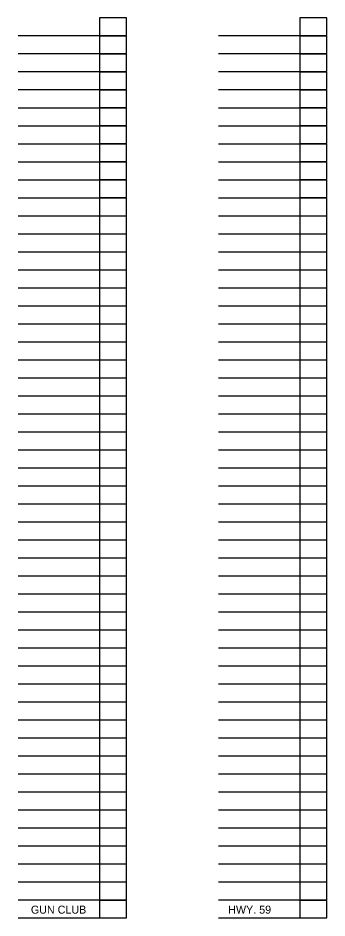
# Model space of a CAD drawing. Extents: x 625451 to 4181825, y 337941 to 441164.
# Drawn here: x 719151 to 726863, y 373673 to 396164 of the extents above; entities that cross this region are included whole.
import ezdxf

# ---------------------------------------------------------------- set-up
doc = ezdxf.new("R2010")
doc.units = 0
for name, color, linetype in [('PLOT_BDR-NOTUSED', 7, 'Continuous'), ('R_CX_LAYOUT-GC', 7, 'Continuous'), ('R_CX_Layout-Hwy59', 7, 'Continuous'), ('R_No Plot_SEG2_FR', 7, 'Continuous')]:
    doc.layers.add(name, color=color, linetype=linetype)

msp = doc.modelspace()

# ---------------------------------------------------------------- linework, layer by layer
at = {"layer": 'PLOT_BDR-NOTUSED'}
for points in [[(721862, 396164), (721182, 396164), (721182, 395724), (721862, 395724)], [(726863, 396164), (726183, 396164), (726183, 395724), (726863, 395724)], [(721862, 395714), (721182, 395714), (721182, 395274), (721862, 395274)], [(726863, 395714), (726183, 395714), (726183, 395274), (726863, 395274)], [(721862, 395264), (721182, 395264), (721182, 394824), (721862, 394824)], [(726863, 395264), (726183, 395264), (726183, 394824), (726863, 394824)], [(721862, 394814), (721182, 394814), (721182, 394374), (721862, 394374)], [(726863, 394814), (726183, 394814), (726183, 394374), (726863, 394374)], [(721862, 394364), (721182, 394364), (721182, 393924), (721862, 393924)], [(726863, 394364), (726183, 394364), (726183, 393924), (726863, 393924)], [(721862, 393914), (721182, 393914), (721182, 393474), (721862, 393474)], [(726863, 393914), (726183, 393914), (726183, 393474), (726863, 393474)], [(721862, 393464), (721182, 393464), (721182, 393024), (721862, 393024)], [(726863, 393464), (726183, 393464), (726183, 393024), (726863, 393024)], [(721862, 393014), (721182, 393014), (721182, 392574), (721862, 392574)], [(726863, 393014), (726183, 393014), (726183, 392574), (726863, 392574)], [(721862, 392564), (721182, 392564), (721182, 392124), (721862, 392124)], [(726863, 392564), (726183, 392564), (726183, 392124), (726863, 392124)], [(721862, 392114), (721182, 392114), (721182, 391674), (721862, 391674)], [(726863, 392114), (726183, 392114), (726183, 391674), (726863, 391674)], [(721862, 391664), (721182, 391664), (721182, 391224), (721862, 391224)], [(726863, 391664), (726183, 391664), (726183, 391224), (726863, 391224)], [(721862, 391214), (721182, 391214), (721182, 390774), (721862, 390774)], [(726863, 391214), (726183, 391214), (726183, 390774), (726863, 390774)], [(721862, 390764), (721182, 390764), (721182, 390324), (721862, 390324)], [(726863, 390764), (726183, 390764), (726183, 390324), (726863, 390324)], [(721862, 390314), (721182, 390314), (721182, 389874), (721862, 389874)], [(726863, 390314), (726183, 390314), (726183, 389874), (726863, 389874)], [(721862, 389864), (721182, 389864), (721182, 389424), (721862, 389424)], [(726863, 389864), (726183, 389864), (726183, 389424), (726863, 389424)], [(721862, 389414), (721182, 389414), (721182, 388974), (721862, 388974)], [(726863, 389414), (726183, 389414), (726183, 388974), (726863, 388974)], [(721862, 388964), (721182, 388964), (721182, 388524), (721862, 388524)], [(726863, 388964), (726183, 388964), (726183, 388524), (726863, 388524)], [(721862, 388514), (721182, 388514), (721182, 388074), (721862, 388074)], [(726863, 388514), (726183, 388514), (726183, 388074), (726863, 388074)], [(721862, 388064), (721182, 388064), (721182, 387624), (721862, 387624)], [(726863, 388064), (726183, 388064), (726183, 387624), (726863, 387624)], [(721862, 387614), (721182, 387614), (721182, 387174), (721862, 387174)], [(726863, 387614), (726183, 387614), (726183, 387174), (726863, 387174)], [(721862, 387164), (721182, 387164), (721182, 386724), (721862, 386724)], [(726863, 387164), (726183, 387164), (726183, 386724), (726863, 386724)], [(721862, 386714), (721182, 386714), (721182, 386274), (721862, 386274)], [(726863, 386714), (726183, 386714), (726183, 386274), (726863, 386274)], [(726863, 386264), (726183, 386264), (726183, 385824), (726863, 385824)], [(726863, 385814), (726183, 385814), (726183, 385374), (726863, 385374)], [(726863, 385364), (726183, 385364), (726183, 384924), (726863, 384924)], [(726863, 384914), (726183, 384914), (726183, 384474), (726863, 384474)], [(726863, 384464), (726183, 384464), (726183, 384024), (726863, 384024)], [(726863, 384014), (726183, 384014), (726183, 383574), (726863, 383574)], [(726863, 383564), (726183, 383564), (726183, 383124), (726863, 383124)], [(726863, 383114), (726183, 383114), (726183, 382674), (726863, 382674)], [(726863, 382664), (726183, 382664), (726183, 382224), (726863, 382224)], [(726863, 382214), (726183, 382214), (726183, 381774), (726863, 381774)], [(726863, 381764), (726183, 381764), (726183, 381324), (726863, 381324)], [(726863, 381314), (726183, 381314), (726183, 380874), (726863, 380874)], [(726863, 380864), (726183, 380864), (726183, 380424), (726863, 380424)], [(726863, 380414), (726183, 380414), (726183, 379974), (726863, 379974)], [(726863, 379964), (726183, 379964), (726183, 379524), (726863, 379524)], [(726863, 379514), (726183, 379514), (726183, 379074), (726863, 379074)], [(726863, 379064), (726183, 379064), (726183, 378624), (726863, 378624)], [(726863, 378614), (726183, 378614), (726183, 378174), (726863, 378174)], [(726863, 378164), (726183, 378164), (726183, 377724), (726863, 377724)], [(726863, 377714), (726183, 377714), (726183, 377274), (726863, 377274)]]:
    msp.add_lwpolyline(points, close=True, dxfattribs=at)
at = {"layer": 'R_CX_LAYOUT-GC'}
for p, q in [((719151, 395723), (721250, 395723)), ((719151, 395273), (721250, 395273)), ((719151, 394823), (721250, 394823)), ((719151, 394373), (721250, 394373)), ((719151, 393923), (721250, 393923)), ((719151, 393473), (721250, 393473)), ((719151, 393023), (721250, 393023)), ((719151, 392573), (721250, 392573)), ((719151, 392123), (721250, 392123)), ((719151, 391673), (721250, 391673)), ((719151, 391223), (721250, 391223)), ((719151, 390773), (721250, 390773)), ((719151, 390323), (721250, 390323)), ((719151, 389873), (721250, 389873)), ((719151, 389423), (721250, 389423)), ((719151, 388973), (721250, 388973)), ((719151, 388523), (721250, 388523)), ((719151, 388073), (721250, 388073)), ((719151, 387623), (721250, 387623)), ((719151, 387173), (721250, 387173)), ((719151, 386723), (721250, 386723)), ((719151, 386273), (721250, 386273)), ((719151, 385823), (721250, 385823)), ((719151, 385373), (721250, 385373)), ((719151, 384923), (721250, 384923)), ((719151, 384473), (721250, 384473)), ((719151, 384023), (721250, 384023)), ((719151, 383573), (721250, 383573)), ((719151, 383123), (721250, 383123)), ((719151, 382673), (721250, 382673)), ((719151, 382223), (721250, 382223)), ((719151, 381773), (721250, 381773)), ((719151, 381323), (721250, 381323)), ((719151, 380873), (721250, 380873)), ((719151, 380423), (721250, 380423)), ((719151, 379973), (721250, 379973)), ((719151, 379523), (721250, 379523)), ((719151, 379073), (721250, 379073)), ((719151, 378623), (721250, 378623)), ((719151, 378173), (721250, 378173)), ((719151, 377723), (721250, 377723)), ((719151, 377273), (721250, 377273)), ((719151, 376823), (721250, 376823)), ((719151, 376373), (721250, 376373)), ((719151, 375923), (721250, 375923)), ((719151, 375473), (721250, 375473)), ((719151, 375023), (721250, 375023)), ((719151, 374573), (721250, 374573)), ((719151, 374123), (721250, 374123)), ((719151, 373673), (721250, 373673))]:
    msp.add_line(p, q, dxfattribs=at)
at = {"layer": 'R_CX_Layout-Hwy59'}
for p, q in [((724152, 395723), (726251, 395723)), ((724152, 395273), (726251, 395273)), ((724152, 394823), (726251, 394823)), ((724152, 394373), (726251, 394373)), ((724152, 393923), (726251, 393923)), ((724152, 393473), (726251, 393473)), ((724152, 393023), (726251, 393023)), ((724152, 392573), (726251, 392573)), ((724152, 392123), (726251, 392123)), ((724152, 391673), (726251, 391673)), ((724152, 391223), (726251, 391223)), ((724152, 390773), (726251, 390773)), ((724152, 390323), (726251, 390323)), ((724152, 389873), (726251, 389873)), ((724152, 389423), (726251, 389423)), ((724152, 388973), (726251, 388973)), ((724152, 388523), (726251, 388523)), ((724152, 388073), (726251, 388073)), ((724152, 387623), (726251, 387623)), ((724152, 387173), (726251, 387173)), ((724152, 386723), (726251, 386723)), ((724152, 386273), (726251, 386273)), ((724152, 385823), (726251, 385823)), ((724152, 385373), (726251, 385373)), ((724152, 384923), (726251, 384923)), ((724152, 384473), (726251, 384473)), ((724152, 384023), (726251, 384023)), ((724152, 383573), (726251, 383573)), ((724152, 383123), (726251, 383123)), ((724152, 382673), (726251, 382673)), ((724152, 382223), (726251, 382223)), ((724152, 381773), (726251, 381773)), ((724152, 381323), (726251, 381323)), ((724152, 380873), (726251, 380873)), ((724152, 380423), (726251, 380423)), ((724152, 379973), (726251, 379973)), ((724152, 379523), (726251, 379523)), ((724152, 379073), (726251, 379073)), ((724152, 378623), (726251, 378623)), ((724152, 378173), (726251, 378173)), ((724152, 377723), (726251, 377723)), ((724152, 377273), (726251, 377273)), ((724152, 376823), (726251, 376823)), ((724152, 376373), (726251, 376373)), ((724152, 375923), (726251, 375923)), ((724152, 375473), (726251, 375473)), ((724152, 375023), (726251, 375023)), ((724152, 374573), (726251, 374573)), ((724152, 374123), (726251, 374123)), ((724152, 373673), (726251, 373673))]:
    msp.add_line(p, q, dxfattribs=at)
at = {"layer": 'R_No Plot_SEG2_FR'}
for points in [[(721862, 386264), (721182, 386264), (721182, 385824), (721862, 385824)], [(721862, 385814), (721182, 385814), (721182, 385374), (721862, 385374)], [(721862, 385364), (721182, 385364), (721182, 384924), (721862, 384924)], [(721862, 384914), (721182, 384914), (721182, 384474), (721862, 384474)], [(721862, 384464), (721182, 384464), (721182, 384024), (721862, 384024)], [(721862, 384014), (721182, 384014), (721182, 383574), (721862, 383574)], [(721862, 383564), (721182, 383564), (721182, 383124), (721862, 383124)], [(721862, 383114), (721182, 383114), (721182, 382674), (721862, 382674)], [(721862, 382664), (721182, 382664), (721182, 382224), (721862, 382224)], [(721862, 382214), (721182, 382214), (721182, 381774), (721862, 381774)], [(721862, 381764), (721182, 381764), (721182, 381324), (721862, 381324)], [(721862, 381314), (721182, 381314), (721182, 380874), (721862, 380874)], [(721862, 380864), (721182, 380864), (721182, 380424), (721862, 380424)], [(721862, 380414), (721182, 380414), (721182, 379974), (721862, 379974)], [(721862, 379964), (721182, 379964), (721182, 379524), (721862, 379524)], [(721862, 379514), (721182, 379514), (721182, 379074), (721862, 379074)], [(721862, 379064), (721182, 379064), (721182, 378624), (721862, 378624)], [(721862, 378614), (721182, 378614), (721182, 378174), (721862, 378174)], [(721862, 378164), (721182, 378164), (721182, 377724), (721862, 377724)], [(721862, 377714), (721182, 377714), (721182, 377274), (721862, 377274)], [(721862, 377264), (721182, 377264), (721182, 376824), (721862, 376824)], [(726863, 377264), (726183, 377264), (726183, 376824), (726863, 376824)], [(721862, 376814), (721182, 376814), (721182, 376374), (721862, 376374)], [(726863, 376814), (726183, 376814), (726183, 376374), (726863, 376374)], [(721862, 376364), (721182, 376364), (721182, 375924), (721862, 375924)], [(726863, 376364), (726183, 376364), (726183, 375924), (726863, 375924)], [(721862, 375914), (721182, 375914), (721182, 375474), (721862, 375474)], [(726863, 375914), (726183, 375914), (726183, 375474), (726863, 375474)], [(721862, 375464), (721182, 375464), (721182, 375024), (721862, 375024)], [(726863, 375464), (726183, 375464), (726183, 375024), (726863, 375024)], [(721862, 375014), (721182, 375014), (721182, 374574), (721862, 374574)], [(726863, 375014), (726183, 375014), (726183, 374574), (726863, 374574)], [(721862, 374564), (721182, 374564), (721182, 374124), (721862, 374124)], [(726863, 374564), (726183, 374564), (726183, 374124), (726863, 374124)], [(721862, 374114), (721182, 374114), (721182, 373674), (721862, 373674)], [(726863, 374114), (726183, 374114), (726183, 373674), (726863, 373674)]]:
    msp.add_lwpolyline(points, close=True, dxfattribs=at)

# ---------------------------------------------------------------- texts
at = {"layer": 'R_CX_LAYOUT-GC'}
msp.add_text('GUN CLUB', height=200, dxfattribs=at).set_placement((719472, 373781))
at = {"layer": 'R_CX_Layout-Hwy59'}
msp.add_text('HWY. 59', height=200, dxfattribs=at).set_placement((724398, 373781))

doc.saveas('drawing.dxf')
